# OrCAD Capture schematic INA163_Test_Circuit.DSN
size A; title: INA163, Low-Noise, Low-Distortion  INSTRUMENTATION AMPLIFIER; rev: 1.1; note: Datasheet : SBOS177D EVM : N/A
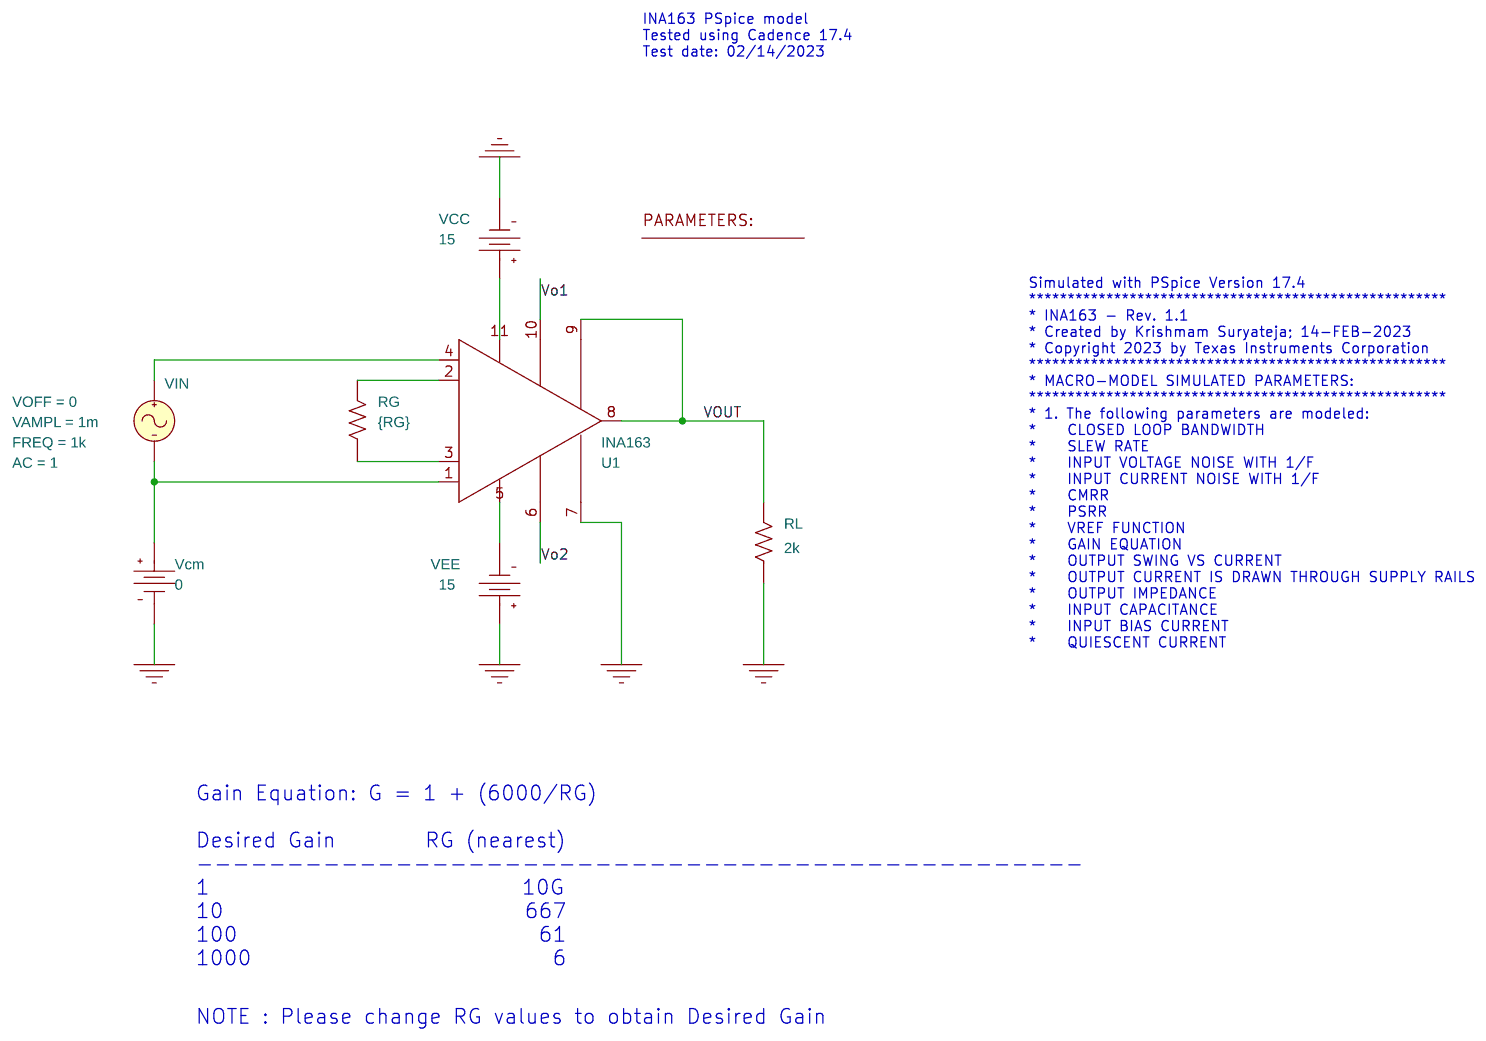
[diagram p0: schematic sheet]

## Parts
1  PARAM
RG  {RG}  [AX/RC05]
RL  2k  [AX/RC05]
U1  INA163
VCC  VDC
Vcm  VDC
VEE  VDC
VIN  VSIN

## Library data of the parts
1 = PARAM: RG: 10G
RG RL = R
U1 = INA163
VCC VEE = VDC: DC: 15
Vcm = VDC: DC: 0
VIN = VSIN: AC: 1; FREQ: 1k; VAMPL: 1m; VOFF: 0

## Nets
0: RL.1 U1.7(REF) VCC.1(-) Vcm.1(-) VEE.0(+)
Vo1: U1.10(VO1)
Vo2: U1.6(VO2)
VOUT: RL.2 U1.8(OUT) U1.9(SENSE)
N14300126: RG.2 U1.2(RG+)
N14300130: RG.1 U1.3(RG-)
N14300245: U1.1(+) Vcm.0(+) VIN.2(-)
N14300266: U1.4(-) VIN.1(+)
N14300680: U1.11(V+) VCC.0(+)
N14300699: U1.5(V-) VEE.1(-)

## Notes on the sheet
- INA163 PSpice model
  Tested using Cadence 17.4
  Test date: 02/14/2023
- Simulated with PSpice Version 17.4
  ******************************************************
  * INA163 - Rev. 1.1
  * Created by Krishmam Suryateja; 14-FEB-2023
  * Copyright 2023 by Texas Instruments Corporation
  ******************************************************
  * MACRO-MODEL SIMULATED PARAMETERS:
  ******************************************************
  * 1. The following parameters are modeled:
  *    CLOSED LOOP BANDWIDTH
  *    SLEW RATE
  *    INPUT VOLTAGE NOISE WITH 1/F
  *    INPUT CURRENT NOISE WITH 1/F
  *    CMRR
  *    PSRR
  *    VREF FUNCTION
  *    GAIN EQUATION
  *    OUTPUT SWING VS CURRENT
  *    OUTPUT CURRENT IS DRAWN THROUGH SUPPLY RAILS
  *    OUTPUT IMPEDANCE
  *    INPUT CAPACITANCE
  *    INPUT BIAS CURRENT
  *    QUIESCENT CURRENT
- Gain Equation: G = 1 + (6000/RG)
  Desired Gain        RG (nearest)
  -------------------------------------------------
  1                            10G
  10                           667
  100                           61
  1000                           6
- NOTE : Please change RG values to obtain Desired Gain
